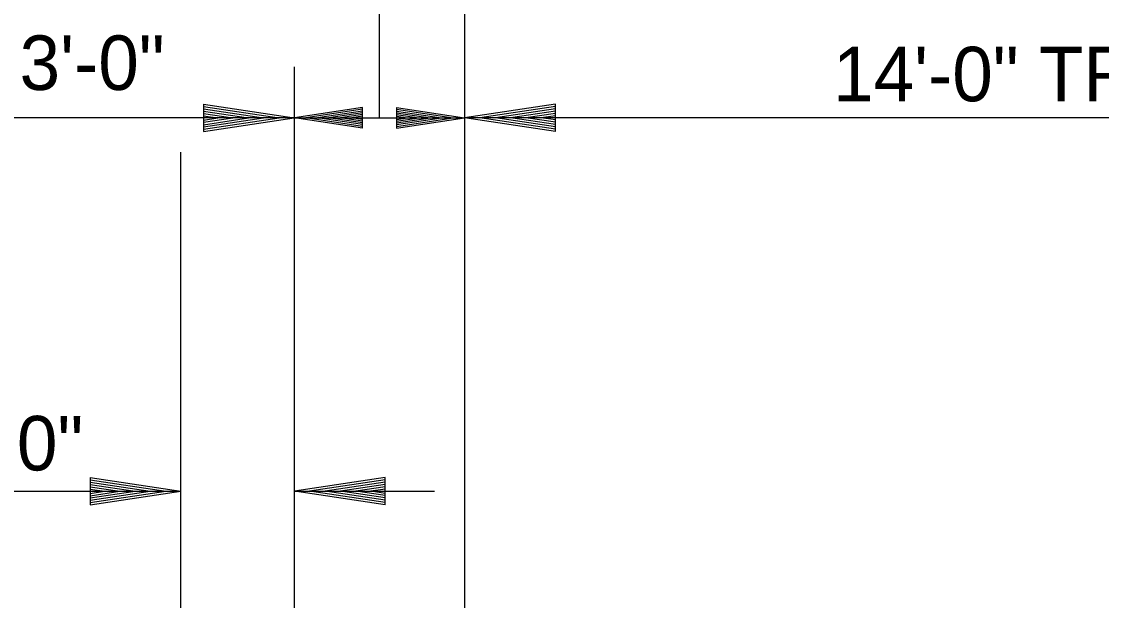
# Model space of a CAD drawing. Extents: x 634177 to 635904, y 289936 to 290970.
# Drawn here: x 635679.73 to 635691.62, y 290461.99 to 290468.36 of the extents above; entities that cross this region are included whole.
import ezdxf

# ---------------------------------------------------------------- set-up
doc = ezdxf.new("R2010")
doc.units = 0
for name, color, linetype in [('Level 13', 7, 'Continuous'), ('Level 43', 7, 'Continuous'), ('R_Dimension', 7, 'Continuous')]:
    doc.layers.add(name, color=color, linetype=linetype)

msp = doc.modelspace()

# ---------------------------------------------------------------- linework, layer by layer
at = {"layer": 'Level 43'}
for p, q in [((635684.611, 290459.366), (635684.611, 290485.402)), ((635683.673, 290467.305), (635683.673, 290480.076)), ((635682.735, 290459.366), (635682.735, 290467.865)), ((635682.734, 290467.305), (635678.484, 290467.305)), ((635682.734, 290467.305), (635678.484, 290467.305)), ((635682.735, 290467.305), (635684.61, 290467.305)), ((635702.111, 290467.305), (635684.61, 290467.305)), ((635681.486, 290459.396), (635681.486, 290466.926)), ((635678.648, 290463.195), (635681.486, 290463.195)), ((635682.735, 290463.195), (635684.277, 290463.195))]:
    msp.add_line(p, q, dxfattribs=at)
at = {"layer": 'R_Dimension'}
for p, q in [((635681.734, 290467.455), (635682.734, 290467.305)), ((635681.734, 290467.455), (635681.734, 290467.155)), ((635681.734, 290467.455), (635682.734, 290467.305)), ((635681.734, 290467.455), (635681.734, 290467.155)), ((635681.734, 290467.43), (635682.567, 290467.305)), ((635681.734, 290467.43), (635682.567, 290467.305)), ((635681.734, 290467.404), (635682.395, 290467.305)), ((635681.734, 290467.404), (635682.395, 290467.305)), ((635683.485, 290467.418), (635682.735, 290467.305)), ((635683.485, 290467.399), (635682.86, 290467.305)), ((635683.485, 290467.193), (635683.485, 290467.418)), ((635683.86, 290467.418), (635684.61, 290467.305)), ((635683.86, 290467.418), (635683.86, 290467.193)), ((635683.86, 290467.399), (635684.485, 290467.305)), ((635685.61, 290467.455), (635684.61, 290467.305)), ((635685.61, 290467.43), (635684.777, 290467.305)), ((635685.61, 290467.405), (635684.949, 290467.305)), ((635685.61, 290467.155), (635685.61, 290467.455)), ((635681.734, 290467.379), (635682.229, 290467.305)), ((635681.734, 290467.379), (635682.229, 290467.305)), ((635681.734, 290467.353), (635682.059, 290467.305)), ((635681.734, 290467.353), (635682.059, 290467.305)), ((635681.734, 290467.328), (635681.892, 290467.305)), ((635681.734, 290467.328), (635681.892, 290467.305)), ((635681.734, 290467.155), (635682.734, 290467.305)), ((635681.734, 290467.256), (635682.059, 290467.305)), ((635681.734, 290467.205), (635682.395, 290467.305)), ((635681.734, 290467.18), (635682.567, 290467.305)), ((635681.734, 290467.23), (635682.229, 290467.305)), ((635681.734, 290467.281), (635681.892, 290467.305)), ((635681.734, 290467.155), (635682.734, 290467.305)), ((635681.734, 290467.256), (635682.059, 290467.305)), ((635681.734, 290467.205), (635682.395, 290467.305)), ((635681.734, 290467.18), (635682.567, 290467.305)), ((635681.734, 290467.23), (635682.229, 290467.305)), ((635681.734, 290467.281), (635681.892, 290467.305)), ((635683.485, 290467.193), (635682.735, 290467.305)), ((635683.485, 290467.211), (635682.86, 290467.305)), ((635683.485, 290467.38), (635682.989, 290467.305)), ((635683.485, 290467.231), (635682.989, 290467.305)), ((635683.485, 290467.361), (635683.114, 290467.305)), ((635683.485, 290467.249), (635683.114, 290467.305)), ((635683.485, 290467.342), (635683.241, 290467.305)), ((635683.485, 290467.269), (635683.241, 290467.305)), ((635683.485, 290467.323), (635683.367, 290467.305)), ((635683.485, 290467.288), (635683.367, 290467.305)), ((635683.86, 290467.38), (635684.356, 290467.305)), ((635683.86, 290467.361), (635684.231, 290467.305)), ((635683.86, 290467.342), (635684.104, 290467.305)), ((635683.86, 290467.323), (635683.979, 290467.305)), ((635683.86, 290467.193), (635684.61, 290467.305)), ((635683.86, 290467.268), (635684.104, 290467.305)), ((635683.86, 290467.231), (635684.356, 290467.305)), ((635683.86, 290467.211), (635684.485, 290467.305)), ((635683.86, 290467.249), (635684.231, 290467.305)), ((635683.86, 290467.288), (635683.979, 290467.305)), ((635685.61, 290467.155), (635684.61, 290467.305)), ((635685.61, 290467.18), (635684.777, 290467.305)), ((635685.61, 290467.206), (635684.949, 290467.305)), ((635685.61, 290467.38), (635685.116, 290467.305)), ((635685.61, 290467.231), (635685.116, 290467.305)), ((635685.61, 290467.354), (635685.285, 290467.305)), ((635685.61, 290467.257), (635685.285, 290467.305)), ((635685.61, 290467.329), (635685.452, 290467.305)), ((635685.61, 290467.282), (635685.452, 290467.305)), ((635680.486, 290463.345), (635681.486, 290463.195)), ((635680.486, 290463.345), (635680.486, 290463.045)), ((635683.735, 290463.345), (635682.735, 290463.195)), ((635683.735, 290463.045), (635683.735, 290463.345)), ((635680.486, 290463.32), (635681.319, 290463.195)), ((635680.486, 290463.295), (635681.147, 290463.195)), ((635680.486, 290463.27), (635680.98, 290463.195)), ((635680.486, 290463.244), (635680.811, 290463.195)), ((635683.735, 290463.32), (635682.902, 290463.195)), ((635683.735, 290463.295), (635683.074, 290463.195)), ((635683.735, 290463.27), (635683.241, 290463.195)), ((635683.735, 290463.244), (635683.41, 290463.195)), ((635680.486, 290463.219), (635680.644, 290463.195)), ((635680.486, 290463.045), (635681.486, 290463.195)), ((635680.486, 290463.146), (635680.811, 290463.195)), ((635680.486, 290463.096), (635681.147, 290463.195)), ((635680.486, 290463.07), (635681.319, 290463.195)), ((635680.486, 290463.121), (635680.98, 290463.195)), ((635680.486, 290463.172), (635680.644, 290463.195)), ((635683.735, 290463.045), (635682.735, 290463.195)), ((635683.735, 290463.07), (635682.902, 290463.195)), ((635683.735, 290463.096), (635683.074, 290463.195)), ((635683.735, 290463.121), (635683.241, 290463.195)), ((635683.735, 290463.147), (635683.41, 290463.195)), ((635683.735, 290463.219), (635683.577, 290463.195)), ((635683.735, 290463.172), (635683.577, 290463.195))]:
    msp.add_line(p, q, dxfattribs=at)

# ---------------------------------------------------------------- texts
at = {"layer": 'Level 13'}
for s, p in [('3\'-0"', (635679.709, 290467.612)), ('14\'-0" TRAVEL LANE', (635688.667, 290467.487)), ('1\'-0"', (635678.813, 290463.424))]:
    msp.add_text(s, height=0.6, dxfattribs=at).set_placement(p)

doc.saveas('drawing.dxf')
